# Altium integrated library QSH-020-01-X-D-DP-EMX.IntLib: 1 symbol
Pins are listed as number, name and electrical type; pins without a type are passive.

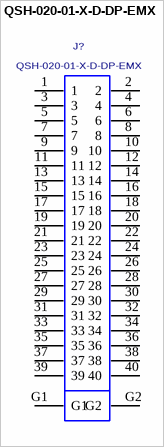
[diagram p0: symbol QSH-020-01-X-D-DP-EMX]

## QSH-020-01-X-D-DP-EMX
designator J?
.5mm EDGE MOUNT DIFFERENTIAL PAIR HIGH SPEED SOCKET ASSEMBLY.; MANUFACTURER: SAMTEC
footprint QSH-020-01-X-D-DP-EMX
pins: 1, 2, 3, 4, 5, 6, 7, 8, 9, 10, 11, 12, 13, 14, 15, 16, 17, 18, 19, 20, 21, 22, 23, 24, 25, 26, 27, 28, 29, 30, 31, 32, 33, 34, 35, 36, 37, 38, 39, 40, G1, G2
